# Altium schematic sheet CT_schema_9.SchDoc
size 274 x 160 mm
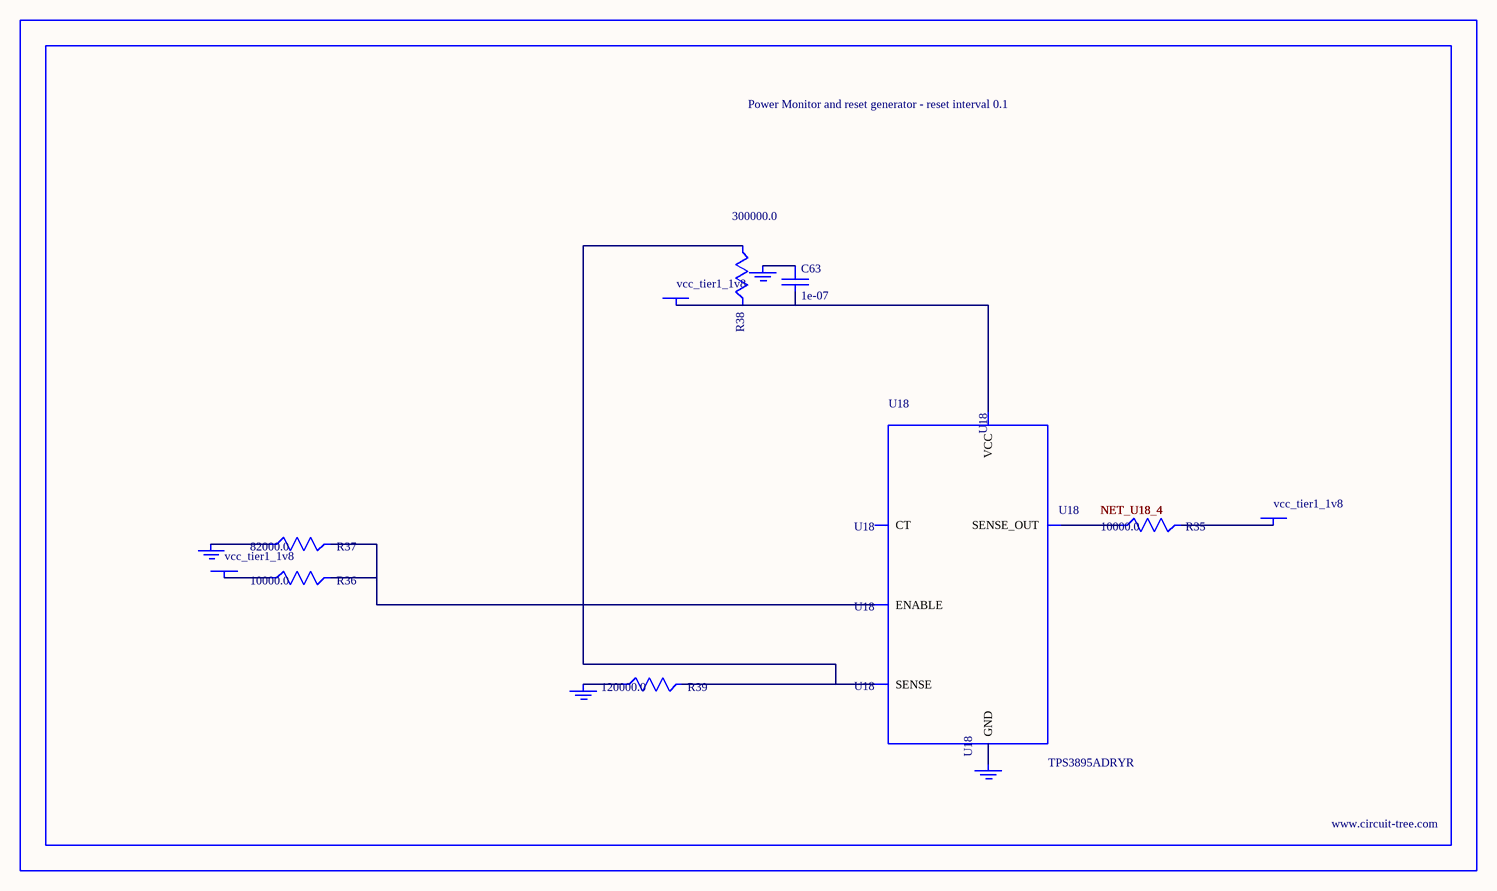
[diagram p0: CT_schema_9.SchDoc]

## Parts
BORDER8  (no value)
C63  1e-07  [C0402]
GND_INSTANCE_8_0  (no value)
GND_INSTANCE_8_1  (no value)
GND_INSTANCE_8_2  (no value)
GND_INSTANCE_8_3  (no value)
POWER_INSTANCE_8_0  vcc_tier1_1v8
POWER_INSTANCE_8_1  vcc_tier1_1v8
POWER_INSTANCE_8_2  vcc_tier1_1v8
R35  10000.0  [R0603]
R36  10000.0  [R0603]
R37  82000.0  [R0603]
R38  300000.0  [R0603]
R39  120000.0  [R0603]
U18  TPS3895ADRYR  [SON-6]

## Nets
NetC63_1: C63.1 GND_INSTANCE_8_2.0(GND)
NetC63_2: C63.2 POWER_INSTANCE_8_2.0(PWR) R38.2 U18.6(VCC)
NetGND_INSTANCE_8_0_0: GND_INSTANCE_8_0.0(GND) R37.1
NetGND_INSTANCE_8_1_0: GND_INSTANCE_8_1.0(GND) R39.1
NetGND_INSTANCE_8_3_0: GND_INSTANCE_8_3.0(GND) U18.2(GND)
NetPOWER_INSTANCE_8_0_0: POWER_INSTANCE_8_0.0(PWR) R36.1
NetPOWER_INSTANCE_8_1_0: POWER_INSTANCE_8_1.0(PWR) R35.2
NetR35_1: R35.1 U18.4(SENSE_OUT)
NetR36_2: R36.2 R37.2 U18.1(ENABLE)
NetR38_1: R38.1 R39.2 U18.3(SENSE)

Not connected (* = marked no-connect by the designer): U18 5(CT)

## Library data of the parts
BORDER8 = BORDER_PAGE8
C63 = C0402C104K3RACTU
GND_INSTANCE_8_0-GND_INSTANCE_8_3 = GND
POWER_INSTANCE_8_0-POWER_INSTANCE_8_2 = PWR
R35 R36 = RC0603JR-0710KL
R37 = RC0603JR-0782KL
R38 = RC0603JR-07300KL
R39 = RC0603JR-07120KL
